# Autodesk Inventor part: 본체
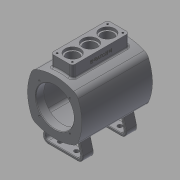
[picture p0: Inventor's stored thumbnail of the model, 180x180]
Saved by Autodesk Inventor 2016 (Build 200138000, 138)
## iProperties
Created: 2015-11
Part Number: 본체
Material: 일반
Document SubType Name: Modeling
Designer: mduedu
Density: 2.71 g/cm^3
Appearance: 기본값
Author: mduedu
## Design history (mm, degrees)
sketch "스케치2"
  geometry: L1 (0, 250)-(0, -250); L2 (250, 0)-(-250, 0); L3 (-50, 50)-(50, 50); L4 (50, 50)-(50, -50); L5 (50, -50)-(-50, -50); L6 (-50, -50)-(-50, 50); A1 r 90 centre (-40, 0) between (40.415, -40.415) and (40.415, 40.415); A2 r 90 centre (40, 0) between (-40.415, 40.415) and (-40.415, -40.415); A3 r 90 centre (0, -40) between (40.415, 40.415) and (-40.415, 40.415); A4 r 90 centre (0, 40) between (-40.415, -40.415) and (40.415, -40.415); 2 further points
  constraints: 12 end point, 8 point on circle, 4 centre point, 4 tangent, 3 perpendicular, 2 horizontal alignment, 2 midpoint, 2 parallel, 2 symmetric about line, 1 coincident, 1 equal radius, 1 horizontal, 1 vertical, 1 vertical alignment, 2 other
  dimensions: "d6" = 500 distance of L1.start L1.end; "d8" = 500 distance of L2.start L2.end; "d9" = 100 distance of L3.end L4.end; "d11" = 90 radius of A3
extrude "돌출1" new body sketch "스케치2" stored distance "d12" = 130; taper "d13" = 0 deg
fillet "모깎기6" dims "d30" = 15
feature "쉘1" dims "d31" = 15, "d32" = 6, "d33" = 15
sketch "스케치5"
  geometry: C1 r 35 at (0, 0); 1 further point
  constraints: 1 centre point, 1 coincident
  dimensions: "d34" = 70 diameter of C1
extrude "돌출3" cut sketch "스케치5" stored distance "d36" = 3; taper "d37" = 0 deg
fillet "모깎기14" dims "d78" = 3
sketch "스케치12"
  geometry: L1 (0, 0)-(28.284, 28.284); L2 (0, 0)-(40, 0); A1 r 40 centre (0, 0) between (28.284, 28.284) and (40, 0); 2 further points
  constraints: 4 end point, 2 coincident, 2 point on circle, 1 centre point, 1 horizontal
  dimensions: "d79" = 80 diameter of A1; "d80" = 45 deg angle of L2 L1
hole "구멍2" sketch "스케치12" at (28.284, 28.284) diameter "d82" = 3.242; stored, may be unused: countersink angle "d86" = 90 deg, drill point angle "d88" = 118 deg; dims "d83" = 9, "d84" = 10, "d85" = 2, "d87" = 11
node "작업 평면2"
sketch "스케치13"
  geometry: L1 (-52.5, -20)-(52.5, -20); L2 (52.5, -20)-(52.5, 20); L3 (52.5, 20)-(-52.5, 20); L4 (-52.5, 20)-(-52.5, -20); L5 (-52.5, -20)-(52.5, 20); L6 (52.5, -20)-(-52.5, 20); 1 further point
  constraints: 12 end point, 2 midpoint, 2 parallel, 1 horizontal, 1 perpendicular
  dimensions: "d93" = 105 distance of L2.end L3.end; "d95" = 40 distance of L1.end L2.end
extrude "돌출8" join sketch "스케치13" stored distance "d96" = 80; taper "d97" = 0 deg
fillet "모깎기15" dims "d98" = 5
fillet "모깎기16" dims "d99" = 3
sketch "스케치14"
  geometry: L1 (-52.5, 15)-(-52.5, -15) reference; L2 (52.5, -15)-(52.5, 15) reference; L3 (-52.5, 0)-(52.5, 0); 4 further points
  constraints: 2 end point, 2 midpoint, 2 point on line, 1 coincident
  dimensions: "d100" = 32 distance of point (-32, 0) point (0, 0); "d102" = 32 distance of point (32, 0) point (0, 0) (derived)
hole "구멍3" sketch "스케치14" at (-32, 0), (0, 0), (32, 0) diameter "d103" = 22; stored, may be unused: countersink angle "d107" = 90 deg, drill point angle "d109" = 118 deg; dims "d104" = 8, "d105" = 28, "d106" = 5, "d108" = 10
sketch "스케치15"
  geometry: L1 (46.5, -14)-(-46.5, -14); L2 (-46.5, -14)-(-46.5, 14); L3 (-46.5, 14)-(46.5, 14); L4 (46.5, 14)-(46.5, -14); L5 (46.5, -14)-(-46.5, 14); L6 (-46.5, -14)-(46.5, 14); L7 (47.5, 20)-(-47.5, 20) reference; L8 (-52.5, 15)-(-52.5, -15) reference; 5 further points
  constraints: 12 end point, 4 coincident, 2 midpoint, 2 parallel, 1 horizontal, 1 perpendicular
  dimensions: "d110" = 6 distance between parallel lines of L3 L7; "d111" = 6 distance between parallel lines of L2 L8
hole "구멍4" sketch "스케치15" at (-46.5, 14), (46.5, 14), (46.5, -14), (-46.5, -14) diameter "d112" = 3.242; stored, may be unused: countersink angle "d116" = 90 deg, drill point angle "d118" = 118 deg; dims "d113" = 10, "d114" = 28, "d115" = 5, "d117" = 13
sketch "스케치16"
  geometry: L1 (33.5, 0)-(61.5, 0) reference; 2 further points
  constraints: 1 vertical alignment, 1 other
  dimensions: "d128" = 11 distance from line of L1 point (47.5, -11)
feature "엠보싱2" sketch "스케치16" dims "d6" = 500, "d8" = 500, "d9" = 100, "d11" = 90, "d34" = 70, "d123" = 0.5, "d124" = 0
chamfer "모따기1" distance "d125" = 1; stored, may be unused: second distance "d126" = 2, angle "d127" = 45 deg
sketch "스케치18"
  geometry: L1 (0, 0)-(0, -80); L2 (40, -80)-(30.531, -44.663); L3 (-40, -80)-(-30.531, -44.663); L4 (-40, -80)-(40, -80); A1 r 90 centre (0, 40) between (-34.941, -42.941) and (34.941, -42.941) reference; A2 r 90 centre (0, 40) between (-30.531, -44.663) and (30.531, -44.663)
  constraints: 8 end point, 3 point on circle, 2 symmetric about line, 1 centre point, 1 coincident, 1 midpoint, 1 perpendicular, 1 vertical
  dimensions: "d132" = 80 distance of L3.start L2.start; "d134" = 75 deg angle of L4 L2; "d136" = 80 distance of L1.start L1.end
extrude "돌출9" new body sketch "스케치18" stored distance "d137" = 100; taper "d138" = 0 deg
fillet "모깎기17" dims "d139" = 10
sketch "스케치19"
  geometry: L1 (26.968, -80)-(-26.968, -80) reference; L2 (-36.627, -67.412)-(-30.531, -44.663) reference; L3 (30.531, -44.663)-(36.627, -67.412) reference; L4 (-25.775, -46.23)-(-31.797, -68.706); L5 (-26.968, -75)-(26.968, -75); L6 (31.797, -68.706)-(25.775, -46.23); L7 (0, 0)-(0, -80); A1 r 10 centre (26.968, -70) between (26.968, -80) and (36.627, -67.412) reference; A2 r 10 centre (-26.968, -70) between (-36.627, -67.412) and (-26.968, -80) reference; A3 r 90 centre (0, 40) between (-30.531, -44.663) and (30.531, -44.663) reference; A4 r 5 centre (-26.968, -70) between (-31.797, -68.706) and (-26.968, -75); A5 r 5 centre (26.968, -70) between (26.968, -75) and (31.797, -68.706); A6 r 90 centre (0, 40) between (-25.775, -46.23) and (25.775, -46.23)
  constraints: 8 end point, 7 point on circle, 3 centre point, 2 parallel, 1 coincident, 1 midpoint, 1 symmetric about line, 1 tangent, 2 other
  dimensions: "d140" = 5 distance between parallel lines of L1 L5
extrude "돌출10" cut sketch "스케치19" stored distance "d141" = 100; taper "d142" = 0 deg
sketch "스케치20"
  geometry: L1 (-30, 0)-(30, 0); L2 (30, 0)-(30, -90); L3 (30, -90)-(-30, -90); L4 (-30, -90)-(-30, 0); L5 (50, -80)-(-50, -80) reference; 2 further points
  constraints: 8 end point, 2 parallel, 1 coincident, 1 horizontal, 1 midpoint, 1 perpendicular
  dimensions: "d143" = 10 distance from line of L5 L2.end; "d144" = 60 distance of L2.end L3.end
extrude "돌출11" cut sketch "스케치20" stored distance "d145" = 100; taper "d146" = 0 deg
sketch "스케치21"
  geometry: L1 (0, 26.968)-(100, 26.968); L2 (100, 53.935)-(100, 0) reference; L3 (0, 0)-(0, 53.935) reference; L4 (0, 53.935)-(20, 53.935) reference; L5 (20, 0)-(0, 0) reference; L6 (115, 76.968)-(-15, 76.968) reference; L7 (115, -23.032)-(-15, -23.032) reference; L8 (10, 53.935)-(10, 0); L9 (50, 76.968)-(50, -23.032); C1 r 4 at (10, 41.968); C2 r 4 at (10, 11.968); C3 r 4 at (90, 41.968); C4 r 4 at (90, 11.968); 2 further points
  constraints: 6 end point, 6 midpoint, 4 centre point, 3 symmetric about line, 1 coincident, 1 horizontal, 1 point on line, 3 other
  dimensions: "d147" = 8 diameter of C1; "d148" = 15 distance from line of C1.centre L1
extrude "돌출12" cut sketch "스케치21" stored distance "d149" = 100; taper "d150" = 0 deg
feature "결합2"
  node "솔리드3"
fillet "모깎기18" dims "d151" = 1
fillet "모깎기19" dims "d152" = 2
node "솔리드1"
pattern_circular "원형 패턴1" dims angle "d90" = 360 deg
mirror "대칭3"
node "투영된 루프1"
